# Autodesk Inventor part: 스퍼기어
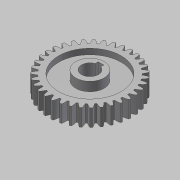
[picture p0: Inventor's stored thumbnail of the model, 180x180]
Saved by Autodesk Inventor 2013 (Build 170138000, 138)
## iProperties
Created: 2013-08
Part Number: 스퍼기어
Material: 강
Document SubType Name: Modeling
Designer: 한국산업디자인학원
Categories: <?xml version="1.0" encoding="UTF-16"?> <MemberInstance><Categories><FamilyTemplate><FamilyTemplateParameter ValueType="xs:double" Id="1" ObjectReferenceKey="da
Density: 1 g/cm^3
CustomPartVersion: 1
Author: 한국산업디자인학원
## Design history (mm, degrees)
sketch "Sketch1"
  geometry: C1 r 37 at (0, 0)
  constraints: 1 centre point
  dimensions: "d0" = 74 diameter of C1 (= da_da)
extrude "Extrusion1" new body sketch "Sketch1" distance "d1" = 15 (= da_b); taper "d2" = 0 deg
workplane "Work Plane2"
feature "피치 지름" dims "d4" = 10, "d5" = 0
workplane "Work Plane8"
workplane "Work Plane9"
feature "스퍼 기어" dims "da_b" = 15, "da_d" = 70, "da_aw" = 70, "da_da" = 74, "da_df" = 65, "da_dw" = 70, angle "da_beta" = 0 deg, "da_lefttooth" = 0, "da_righttooth" = 0
sketch "스케치3"
  geometry: L1 (0, -20)-(0, 20); L2 (-32.5, 0)-(-32.5, 15) reference; L3 (-32.5, 15)-(37, 15) reference; L4 (37, 15)-(37, 0) reference; L5 (37, 0)-(-32.5, 0) reference; L6 (7.5, 18)-(12.5, 18); L7 (12.5, 18)-(12.5, 10); L8 (12.5, 5)-(27.5, 5); L9 (27.5, 10)-(27.5, 15); L10 (27.5, 15)-(35, 15); L11 (35, 0)-(27.5, 0); L12 (27.5, 0)-(27.5, 5); L13 (27.5, 10)-(12.5, 10); L14 (12.5, 5)-(12.5, -13); L15 (12.5, -13)-(7.5, -13); L16 (7.5, -13)-(7.5, 18); L17 (35, 15)-(35, 0); L18 (12.5, 15)-(7.5, 15); L19 (27.5, 15)-(12.5, 15); L20 (27.5, 0)-(12.5, 0); L21 (12.5, 0)-(7.5, 0); 2 further points
  constraints: 34 end point, 10 point on line, 8 perpendicular, 3 parallel, 1 coincident, 1 collinear, 1 midpoint, 1 vertical
  dimensions: "d49" = 40 distance of L1.start L1.end; "d53" = 3 distance between parallel lines of L3 L6; "d54" = 31 distance of L15.end L6.start; "d55" = 15 diameter of L16 L1; "d56" = 25 diameter of L7 L1; "d57" = 25 diameter of L14 L1; "d58" = 55 diameter of L9 L1; "d59" = 55 diameter of L12 L1; "d60" = 70 diameter of L17 L1; "d61" = 5 distance between parallel lines of L13 L3; "d62" = 5 distance of L11.end L8.end
  node "절단 모서리 투영1"
revolve "회전1" stored, may be unused: angle "d63" = 90 deg
revolve "회전2" stored, may be unused: angle "d64" = 90 deg
sketch "스케치4"
  geometry: L1 (-2.5, 7.071)-(-2.5, 9.8); L2 (-2.5, 9.8)-(2.5, 9.8); L3 (2.5, 9.8)-(2.5, 7.071); C1 r 12.5 at (0, 0) reference; A1 r 7.5 centre (0, 0) between (-2.5, 7.071) and (2.5, 7.071); 2 further points
  constraints: 6 end point, 2 point on circle, 1 centre point, 1 coincident, 1 midpoint, 1 parallel, 1 perpendicular, 1 vertical, 1 vertical alignment, 3 other
  dimensions: "d65" = 5 distance of L1.end L2.end; "d67" = 9.8 distance from line of L2 point (0, 0)
extrude "돌출2" cut sketch "스케치4" stored distance "d68" = 10; taper "d69" = 0 deg
body "Solid1"
sketch "Sketch2"
  geometry: C1 r 37 at (0, 0) reference; C2 r 35 at (0, 0)
  constraints: 1 centre point, 1 coincident
  dimensions: "d3" = 70 diameter of C2 (= da_dw)
body "Srf1"
other parameters: "d17" = 0, "d34" = 0.8976 (computed from da_z), "d39" = 0, "d41" = 0, "d47" = 0, "d48" = 0
